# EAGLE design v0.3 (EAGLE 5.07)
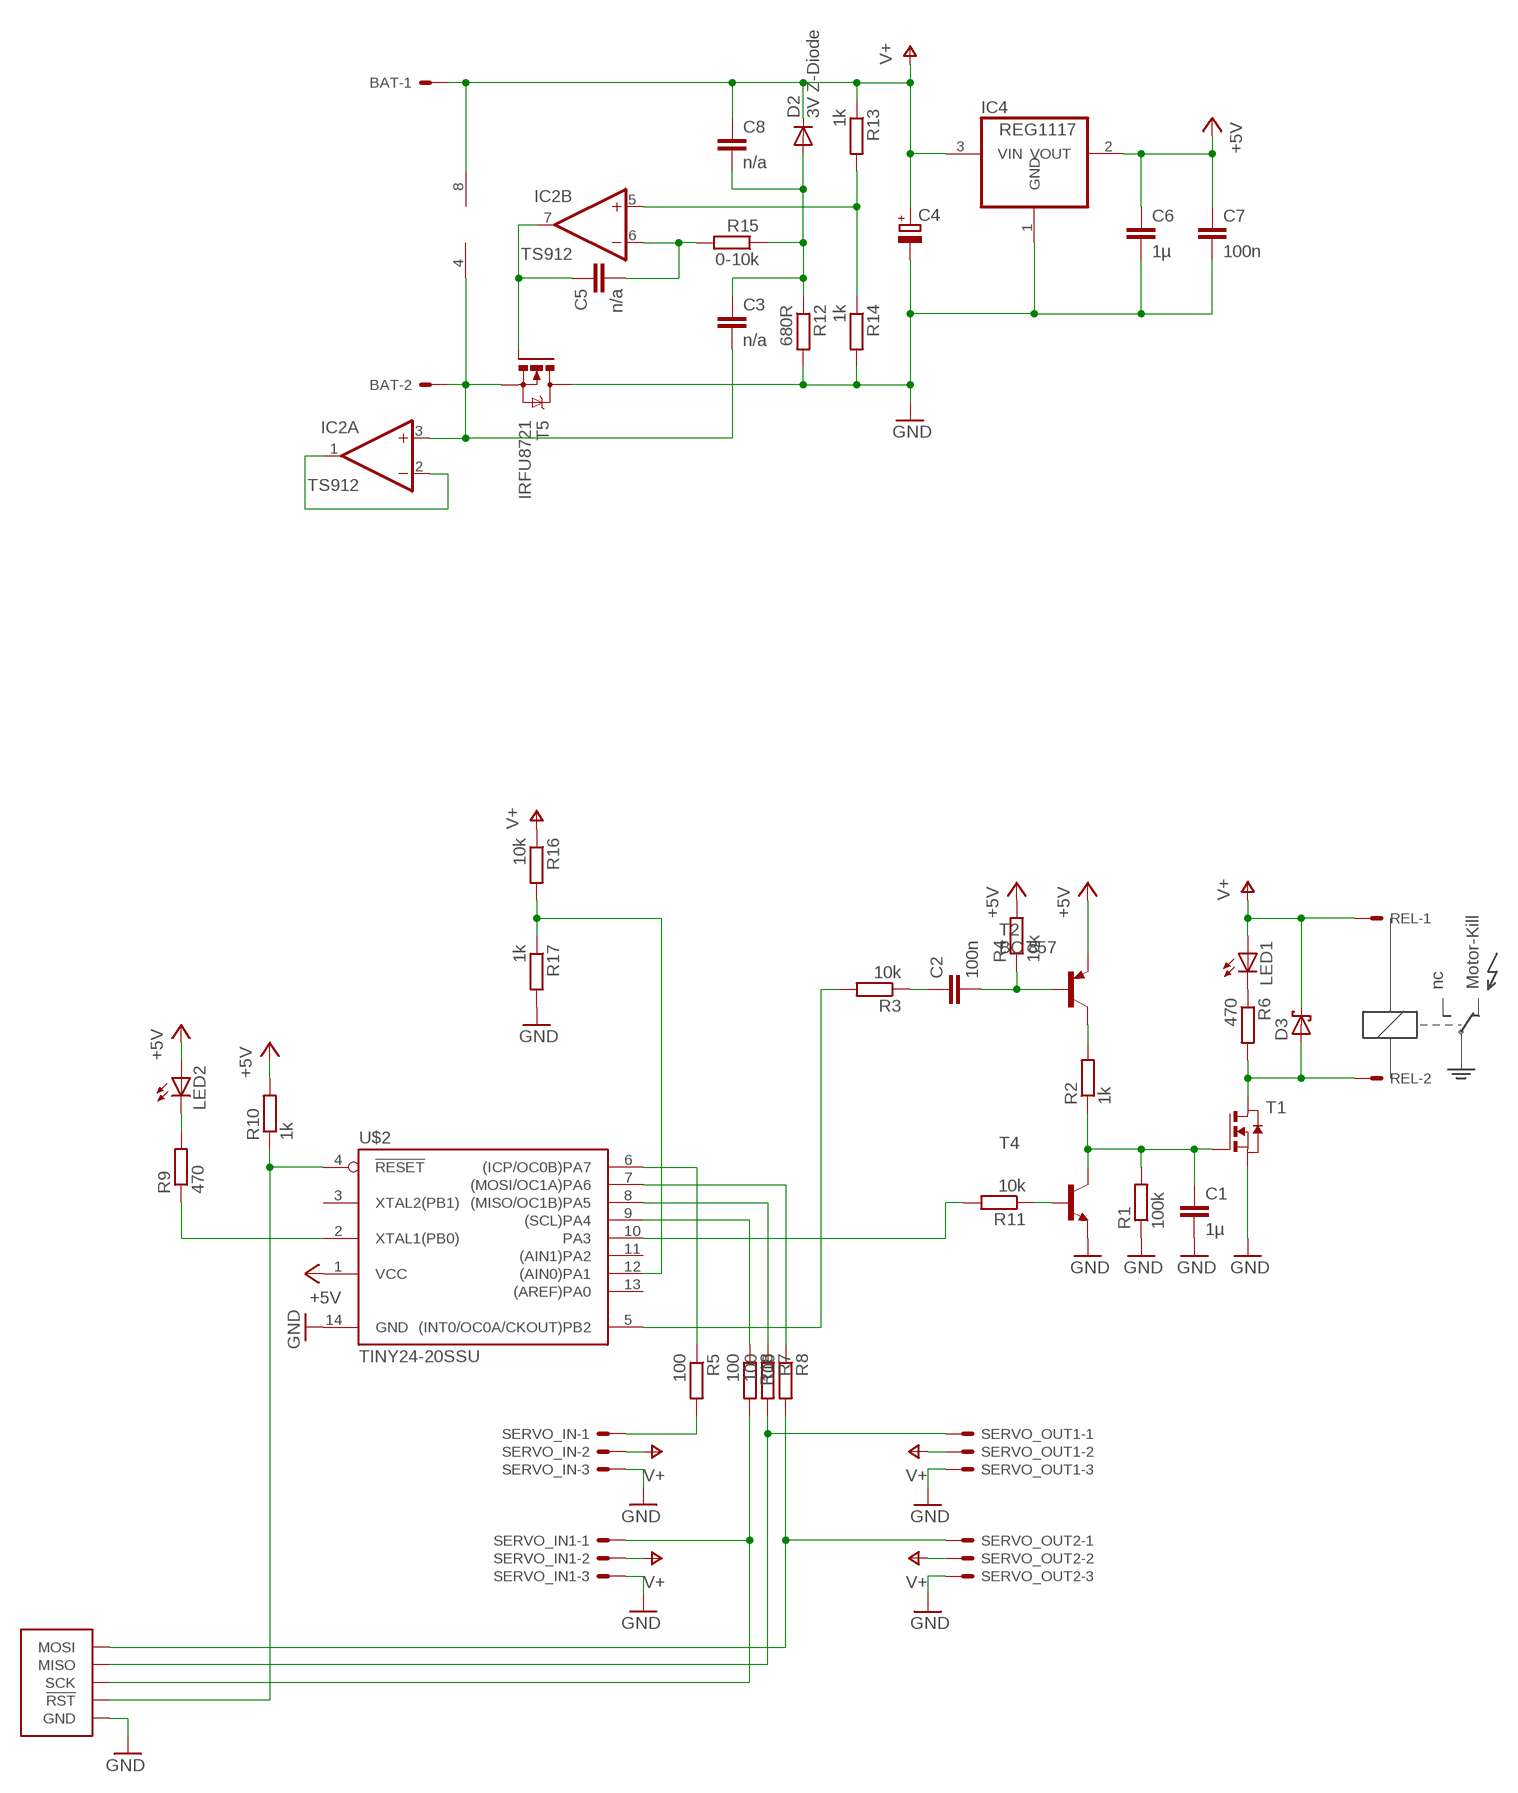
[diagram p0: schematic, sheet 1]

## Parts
BAT  22-23-2021  [22-23-2021]
C1  1µ  C-EUC0805  [C0805]
C2  100n  C-EUC0805  [C0805]
C3  n/a  C-EUC0805K  [C0805K]
C4  CPOL-EUE2.5-7  [E2,5-7]
C5  n/a  C-EUC0805K  [C0805K]
C6  1µ  C-EUC0805  [C0805]
C7  100n  C-EUC0805  [C0805]
C8  n/a  C-EUC0805K  [C0805K]
D2  3V Z-Diode  DIODE-MINIMELF  [MINIMELF]
D3  SCHOTTKY-DIODESMD  [SMB]
IC2  TS912  TL062D  [SO08]
IC4  REG1117  [SOT223]
LED1  LED5MM  [LED5MM]
LED2  LED5MM  [LED5MM]
R1  100k  R-EU_M0805  [M0805]
R2  1k  R-EU_M0805  [M0805]
R3  10k  R-EU_M0805  [M0805]
R4  10k  R-EU_M0805  [M0805]
R5  100  R-EU_M0805  [M0805]
R6  470  R-EU_M0805  [M0805]
R7  100  R-EU_M0805  [M0805]
R8  100  R-EU_M0805  [M0805]
R9  470  R-EU_M0805  [M0805]
R10  1k  R-EU_M0805  [M0805]
R11  10k  R-EU_M0805  [M0805]
R12  680R  R-EU_M0805  [M0805]
R13  1k  R-EU_M0805  [M0805]
R14  1k  R-EU_M0805  [M0805]
R15  0-10k  R-EU_M0805  [M0805]
R16  10k  R-EU_M0805  [M0805]
R17  1k  R-EU_M0805  [M0805]
R18  100  R-EU_M0805  [M0805]
REL  22-23-2021  [22-23-2021]
SERVO_IN  22-23-2031  [22-23-2031]
SERVO_IN1  22-23-2031  [22-23-2031]
SERVO_OUT1  22-23-2031  [22-23-2031]
SERVO_OUT2  22-23-2031  [22-23-2031]
T1  NMOSSOT23  [SOT-23]
T2  BC 857  BC857BSMD  [SOT23-BEC]
T4  BC817-40SMD  [SOT23-BEC]
T5  IRFU8721  [TO251AAV]
U$1  AVR-PROG  [2MM-HEADER]
U$2  TINY24-20SSU  [14S1]

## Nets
+5V: C6.1 C7.1 IC4.2(VOUT) LED2.A R4.2 R10.2 T2.E U$2.1(VCC)
AD_V+: R16.2 R17.1 U$2.12((AIN0)PA1)
GND: C1.2 C4.- C6.2 C7.2 IC4.1(GND) R1.1 R12.2 R14.2 R17.2 SERVO_IN1.3 SERVO_IN.3 SERVO_OUT1.3 SERVO_OUT2.3 T1.2(S) T4.E T5.2(D0) U$1.GND U$2.14(GND)
IN-: BAT.2 C3.2 IC2.3(A:+IN) IC2.4(P:V-) T5.3(S0)
N$1: C1.1 R1.2 R2.1 T1.3(G) T4.C
N$2: D3.A R6.2 REL.2 T1.1(D)
N$3: R2.2 T2.C
N$4: C2.2 R4.1 T2.B
N$5: C2.1 R3.1
N$6: R3.2 U$2.5((INT0/OC0A/CKOUT)PB2)
N$7: R5.1 U$2.6((ICP/OC0B)PA7)
N$8: R5.2 SERVO_IN.1
N$9: R8.2 SERVO_OUT2.1 U$1.MOSI
N$10: R7.2 SERVO_OUT1.1 U$1.MISO
N$11: LED1.K(C) R6.1
N$12: R9.1 U$2.2(XTAL1(PB0))
N$13: R8.1 U$2.7((MOSI/OC1A)PA6)
N$14: LED2.K(C) R9.2
N$15: R7.1 U$2.8((MISO/OC1B)PA5)
N$16: R10.1 U$1./RST(!RST) U$2.4(!RESET)
N$17: R11.1 T4.B
N$18: R11.2 U$2.10(PA3)
N$19: IC2.5(B:+IN) R13.2 R14.1
N$20: R18.1 U$2.9((SCL)PA4)
N$21: C3.1 C8.2 D2.A R12.1 R15.1
N$22: C5.2 IC2.6(B:-IN) R15.2
N$23: C5.1 IC2.7(B:OUT) T5.1(G)
N$24: IC2.1(A:OUT) IC2.2(A:-IN)
N$27: R18.2 SERVO_IN1.1 U$1.SCK
V+: BAT.1 C4.+ C8.1 D2.C D3.C IC2.8(P:V+) IC4.3(VIN) LED1.A R13.1 R16.1 REL.1 SERVO_IN1.2 SERVO_IN.2 SERVO_OUT1.2 SERVO_OUT2.2
Unconnected: U$2.3(XTAL2(PB1)) U$2.11((AIN1)PA2) U$2.13((AREF)PA0)

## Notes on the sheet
- nc | Motor-Kill

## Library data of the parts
BAT REL = con-molex:22-23-2021: .100" (2.54mm) Center Header - 2 Pin
C1-C3 C5-C8 = rcl:C-EU: CAPACITOR, European symbol
C4 = rcl:CPOL-EU: POLARIZED CAPACITOR, European symbol
D2 = diode:DIODE-: DIODE
D3 = diode:SCHOTTKY-DIODE: Schottky Diode
IC2 = linear:TL062: OP AMP
IC4 = burr-brown:REG1117: 800mA and 1A Low Dropout (LDO) Positive Regulator 1.8V, 2.5V, 2.85V, 3.3V, 5V, and Adj
LED1 LED2 = led:LED: LED
R1-R18 = rcl:R-EU_: RESISTOR, European symbol
SERVO_IN SERVO_IN1 SERVO_OUT1 SERVO_OUT2 = con-molex:22-23-2031: .100" (2.54mm) Center Header - 3 Pin
T1 = zetex:NMOSSOT23: MOS FET
T2 = transistor-pnp:BC857*: PNP Transistror
T4 = transistor-npn:BC817*: NPN Transistor
T5 = FET:IRFU8721
U$1 = AVR-prog:AVR-PROG
U$2 = atmel:TINY24

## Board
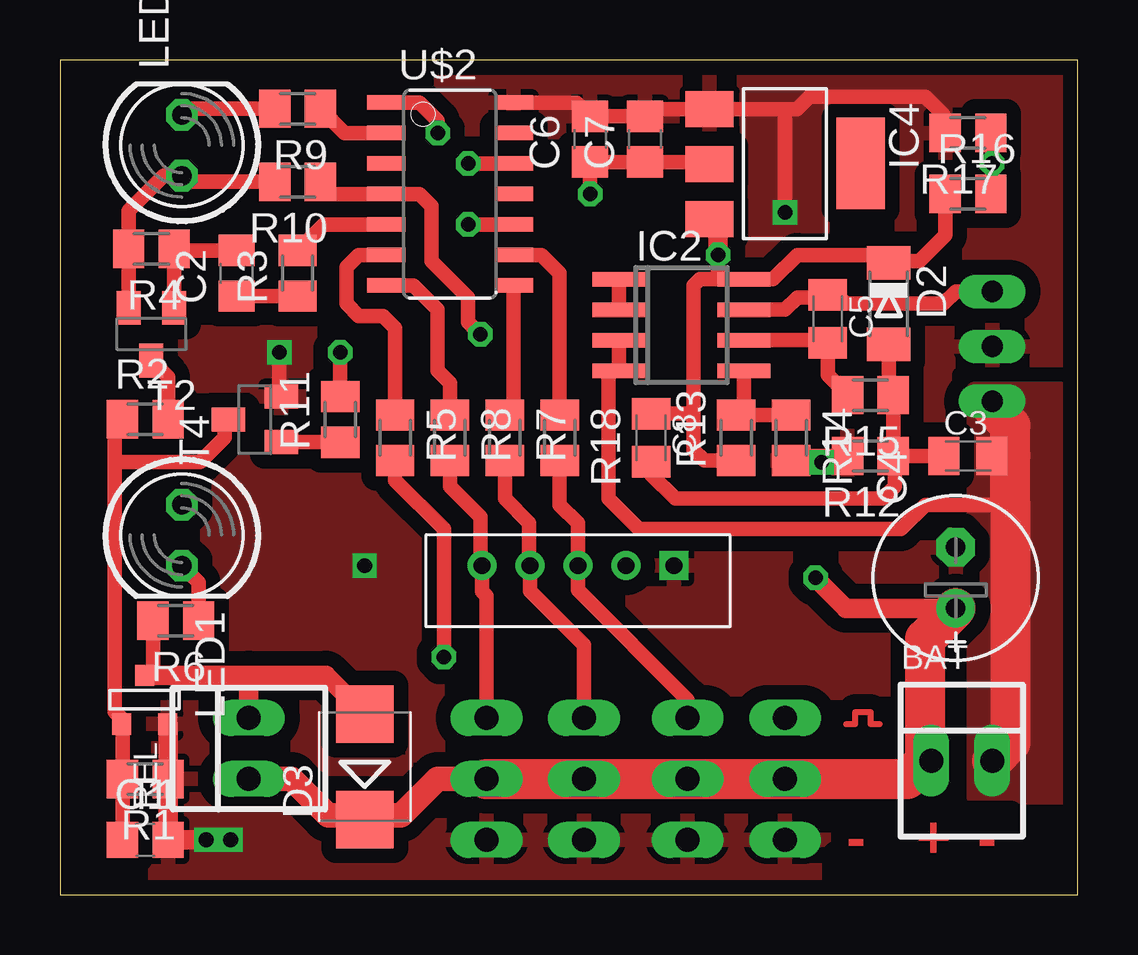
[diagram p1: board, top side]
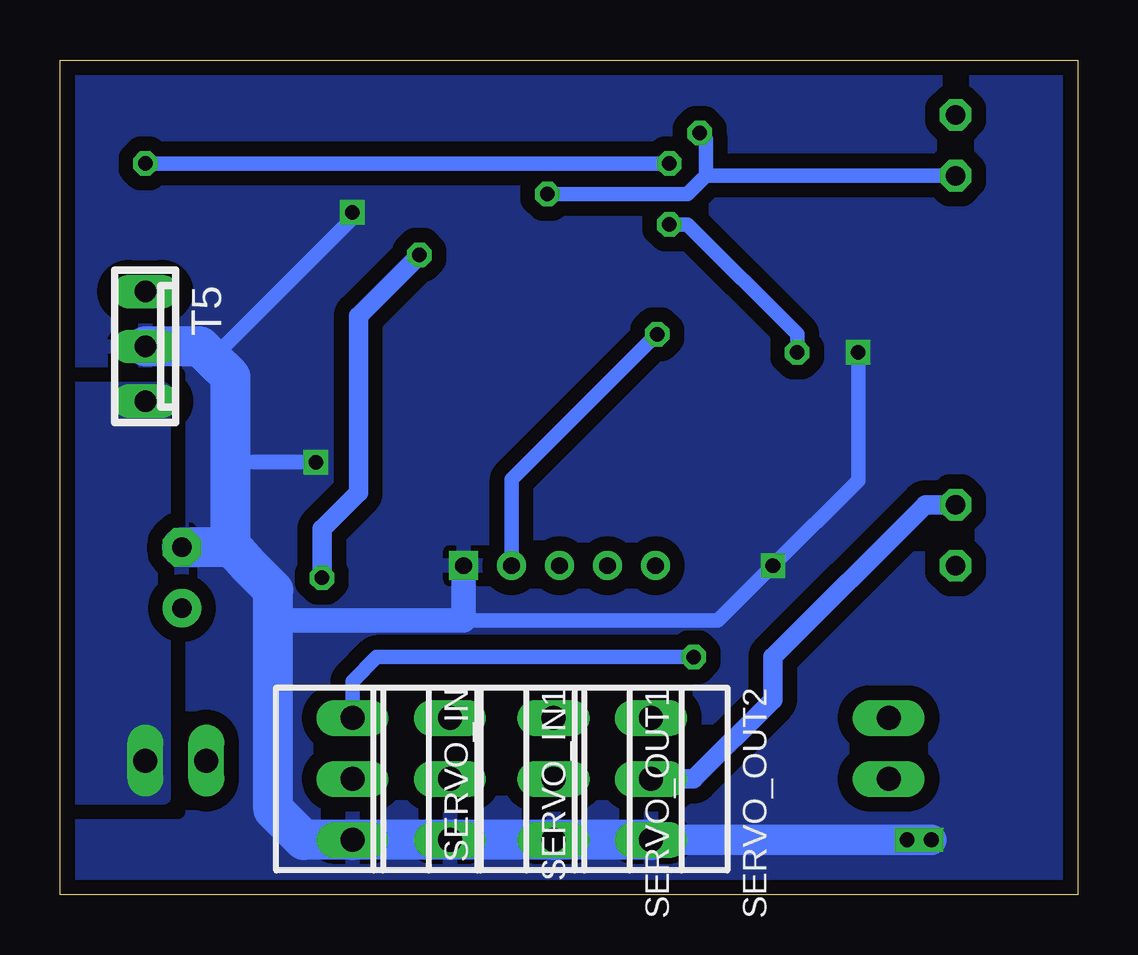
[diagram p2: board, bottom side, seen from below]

Size 42.42 x 34.8 mm. Coordinates in mm from the lower left corner, seen from the top.
Outline: 0,0 42.42,0 42.42,34.8 0,34.8 0,0
Copper layers (1*16): Top 0.035mm / dielectric 1.5mm / Bottom 0.035mm
Design rules "default *": minimum track width 10mil, minimum drill 24mil, track to track 10mil, track to pad 10mil, pad to pad 10mil, via to via 10mil, smd to smd 0mil, copper to edge 5mil, drill to drill 10mil, minimum pad ring 10mil, minimum via ring 8mil, stop-mask expansion 4mil, vias tented up to drill 0mil, thermal gap 10mil
tRestrict: area 32.4,0.6 to 41,1.7

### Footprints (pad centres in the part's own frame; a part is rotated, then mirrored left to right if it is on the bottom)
22-23-2021 = drill 1 long: 1 -1.27,0; 2 1.27,0
C0805 = smd 1.3 x 1.5: 1 -0.95,0; 2 0.95,0
C0805K = smd 1.3 x 1.6: 1 -1,0; 2 1,0
E2,5-7 = drill 0.813 pad 1.6 round: + -1.27,0 | drill 0.813 pad 1.6 octagon: - 1.27,0
MINIMELF = smd 1.4 x 1.8: A 1.7,0; C -1.7,0
SMB = smd 2.4 x 2.4: A 2.2,0; C -2.2,0
SO08 = smd 0.6 x 2.2: 1 -1.905,-2.6; 2 -0.635,-2.6; 3 0.635,-2.6; 4 1.905,-2.6; 5 1.905,2.6; 6 0.635,2.6; 7 -0.635,2.6; 8 -1.905,2.6
SOT223 = smd 1.499 x 2.007: 1 -2.261,-3.15; 2 0.025,-3.15; 3 2.311,-3.15 | smd 3.81 x 2.007: 4 0,3.15
LED5MM = drill 0.813 octagon: A -1.27,0; K 1.27,0
M0805 = smd 1.3 x 1.6: 1 -0.95,0; 2 0.95,0
22-23-2031 = drill 1 long: 1 -2.54,0; 2 0,0; 3 2.54,0
SOT-23 = smd 0.787 x 0.889: 1 0.025,-1.016; 2 -0.94,1.016; 3 0.991,1.016
SOT23-BEC = smd 1 x 1.4: B -0.95,-1.1; C 0,1.1; E 0.95,-1.1
TO251AAV = drill 0.889 long: 1 -2.286,0; 2 0,0; 3 2.286,0
2MM-HEADER = drill 0.7 round: /RST 0,-2; MISO 0,2; MOSI 0,4; SCK 0,0 | drill 0.7 square: GND 0,-4
14S1 = smd 0.6 x 1.6: 1 -3.81,-2.654; 2 -2.54,-2.654; 3 -1.27,-2.654; 4 0,-2.654; 5 1.27,-2.654; 6 2.54,-2.654; 7 3.81,-2.654; 8 3.81,2.654; 9 2.54,2.654; 10 1.27,2.654; 11 0,2.654; 12 -1.27,2.654; 13 -2.54,2.654; 14 -3.81,2.654

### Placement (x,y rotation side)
BAT  37.59,5.59 0 top
C1  3.56,2.29 0 top
C2  7.37,25.91 90 top
C3  37.85,18.29 0 top
C4  37.34,13.21 90 top
C5  32,24 270 top
C6  22.1,31.5 90 top
C7  24.38,31.5 90 top
C8  24.64,19.05 270 top
D2  34.54,24.64 270 top
D3  12.7,5.33 90 top
IC2  25.91,23.75 270 top
IC4  30.23,30.48 270 top
LED1  5.08,14.99 270 top
LED2  5.08,31.24 90 top
R1  3.56,4.83 180 top
R2  3.56,19.81 0 top
R3  9.91,25.91 90 top
R4  3.81,26.92 180 top
R5  13.97,19.05 270 top
R6  4.83,11.43 180 top
R7  18.54,19.05 270 top
R8  16.26,19.05 270 top
R9  9.91,32.77 180 top
R10  9.91,29.72 180 top
R11  11.68,19.81 90 top
R12  33.78,18.29 180 top
R13  28.19,19.05 90 top
R14  30.48,19.05 270 top
R15  33.78,20.83 180 top
R16  37.85,29.21 0 top
R17  37.85,31.75 180 top
R18  20.83,19.05 270 top
REL  7.87,6.1 90 top
SERVO_IN  30.23,4.83 270 bottom
SERVO_IN1  26.16,4.83 270 bottom
SERVO_OUT1  21.84,4.83 270 bottom
SERVO_OUT2  17.78,4.83 270 bottom
T1  3.56,8.13 180 top
T2  3.81,23.37 180 top
T4  8.13,19.81 90 top
T5  38.86,22.86 270 bottom
U$1  21.59,13.72 90 top
U$2  16.26,29.21 270 top

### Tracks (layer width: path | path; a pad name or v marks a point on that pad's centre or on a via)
+5V  (via drill 0.61)
  Top 0.61: R10.2 5.33,29.72 LED2.A 4.32,29.97 2.86,28.51 R4.2 T2.E | IC4.2 26.98,30.55 C7.1 C6.1 v22.1,29.21 | v15.75,31.75 15.75,32.26 14.99,33.02 U$2.1
  Bottom 0.61: v22.1,29.21 16.26,29.21 15.49,29.97 | LED2.A 15.49,29.97 | 15.49,29.97 15.49,31.5 v15.75,31.75
AD_V+  (via drill 0.61)
  Top 0.61: v17.02,30.48 U$2.12 | R16.2 38.86,29.28 v38.86,30.48 38.86,31.68 R17.1
  Bottom 0.61: v17.02,30.48 v38.86,30.48
GND  (via drill 0.61)
  Top 0.61: 30.23,32.74 IC4.1 24.68,32.74 C7.2 C6.2 21.52,33.02 U$2.14 | R17.2 36.83,31.82 36.83,32.51 36.07,33.27 31.24,33.27 30.71,32.74 30.23,32.74 | v30.23,28.45 30.23,32.74 | T4.E 9.14,20.85 v9.14,22.61 | R14.2 30.41,18.29 R12.2 31.75,18.29 v31.75,18.03
  Top 0.813: T1.2 R1.1 C1.2 v6.1,2.29 v7.11,2.29
  Bottom 0.61: v30.23,28.45 30.23,28.19 36.07,22.35 | v9.14,22.61 9.14,17.27 v12.7,13.72 14.99,11.43 25.59,11.43 | 35.31,18.03 v31.75,18.03
  Bottom 1.016: 33.53,11.43 25.59,11.43 U$1.GND
  Bottom 1.27: v6.1,2.29 v7.11,2.29 SERVO_OUT2.3
  Bottom 1.676: 35.22,14.48 34.55,13.72 33.53,12.7 33.53,11.43 33.53,3.56 32.26,2.29 SERVO_IN.3 SERVO_IN1.3 SERVO_OUT1.3 SERVO_OUT2.3 | 35.22,14.48 C4.- | 35.22,14.48 35.31,14.48 35.31,18.03 35.31,21.59 36.07,22.35 36.58,22.86 T5.2
  pour Bottom (isolate 0.61, rank 2): 0,34.8 42.42,34.8 42.42,0 0,0
  pour Top (isolate 0.61, rank 2): 0,34.8 42.42,34.8 42.42,0 0,0
IN-
  Top 0.61: 39.62,16.26 36.07,16.26 35.05,15.24 24.13,15.24 22.86,16.51 22.86,21.84 IC2.4 IC2.3 | 39.62,18.29 C3.2
  Top 1.27: 38.86,20.32 T5.3
  Top 1.676: 38.86,20.32 39.62,19.56 39.62,18.29 39.62,16.26 39.62,6.35 BAT.2
  pour Bottom (isolate 0.61, no thermals): 38.1,21.08 42.42,21.08 42.42,4.06 38.1,4.06
  pour Top (isolate 0.61, no thermals): 38.1,21.08 42.42,21.08 42.42,4.06 38.1,4.06
N$1
  Top 0.61: C1.1 R1.2 2.61,7.07 T1.3 2.56,7.34 2.29,7.62 2.29,18.03 | R2.1 2.29,19.49 2.29,18.03 | T4.C 6.86,19.64 6.86,19.05 5.84,18.03 2.29,18.03
N$2
  Top 0.61: R6.2 3.88,9.33 4.06,9.14
  Top 0.813: T1.1 4.06,9.14 7.87,9.14 | 7.87,9.14 11.09,9.14 D3.A | 7.87,9.14 REL.2
N$3
  Top 0.61: T2.C 4.51,21.57 R2.2
N$4
  Top 0.61: C2.2 4.83,26.86 R4.1 T2.B
N$5
  Top 0.61: C2.1 R3.1
N$6
  Top 0.61: U$2.5 10.99,27.94 R3.2
N$7
  Top 0.61: R5.1 13.97,23.62 13.46,24.13 12.45,24.13 11.94,24.64 11.94,26.16 12.45,26.67 U$2.6
N$8  (via drill 0.61)
  Top 0.61: R5.2 13.97,17.27 16,15.24 v16,9.91
  Bottom 0.61: v16,9.91 29.21,9.91 30.23,8.89 SERVO_IN.1
N$9
  Top 0.61: R8.2 16.26,17.02 17.53,15.75 17.53,13.78 U$1.MOSI 17.59,12.64 17.78,12.45 SERVO_OUT2.1
N$10
  Top 0.61: R7.2 18.54,16.51 19.56,15.49 19.56,13.75 U$1.MISO 19.59,12.67 21.84,10.41 SERVO_OUT1.1
N$11
  Top 0.61: R6.1 5.78,13.02 LED1.K
N$12
  Top 0.61: R9.1 11.87,31.75 U$2.2
N$13
  Top 0.61: U$2.7 14.73,25.4 15.75,24.38 15.75,21.84 16.26,21.34 R8.1
N$14
  Top 0.61: R9.2 5.33,32.77 LED2.K
N$15
  Top 0.61: R7.1 18.91,20.39 U$2.8
N$16  (via drill 0.61)
  Top 0.61: R10.1 11.36,29.21 U$2.4 14.99,29.21 15.49,28.7 15.49,26.42 17.02,24.89 17.02,23.88 v17.53,23.37
  Bottom 0.61: v17.53,23.37 23.59,17.3 U$1./RST
N$17
  Top 0.61: T4.B R11.1
N$18  (via drill 0.61)
  Top 0.61: R11.2 v11.68,22.61 | v17.02,27.94 U$2.10
  Bottom 0.61: v11.68,22.61 11.68,23.37 16.26,27.94 v17.02,27.94
N$19
  Top 0.61: R13.2 28.45,20 | 28.45,20 R14.1 | IC2.5 28.51,20.06 28.45,20
N$20
  Top 0.61: U$2.9 20.07,26.67 20.83,25.91 R18.1
N$21
  Top 0.61: D2.A 34.54,20.64 R15.1 R12.1 | R12.1 C3.1 | C8.2 24.64,17.53 25.65,16.51 34.29,16.51 34.8,17.02 34.8,18.22 R12.1
N$22
  Top 0.61: IC2.6 31.86,23.11 C5.2 32,21.66 R15.2
N$23
  Top 0.61: IC2.7 30.23,24.38 30.73,24.89 31.89,24.89 C5.1 32.4,25 32.77,24.64 36.83,24.64 37.34,25.15 T5.1
N$24
  Top 0.61: IC2.2 IC2.1
N$25
  Top 0.254: 32.77,7.11 33.15,7.11 33.15,7.62 33.78,7.62 33.78,7.11 34.16,7.11
N$27
  Top 0.61: R18.2 20.83,16.26 21.59,15.49 U$1.SCK 21.59,12.7 26.16,8.13 SERVO_IN1.1
V+  (via drill 0.61)
  Top 0.61: R16.1 36.9,27.5 35.81,26.42 34.62,26.42 D2.C 34.21,26.67 30.73,26.67 29.72,25.65 IC2.8 27.43,25.65 | 27.43,25.65 26.67,25.65 26.42,25.4 26.42,20.07 | v27.43,26.67 27.43,25.65 | R13.1 26.86,18.1 26.42,18.54 26.42,20.07 | C8.1 26.4,20.05 26.42,20.07
  Top 0.813: C4.+ 32.77,11.94 v31.5,13.21 | IC4.3 27.43,28.17 v27.43,26.67
  Top 1.016: REL.1 9.65,4.83 11.18,3.3 12.28,3.3 D3.C 12.61,3.3 14.22,3.3 15.75,4.83 SERVO_OUT2.2
  Top 1.422: 36.07,5.59 BAT.1
  Top 1.676: C4.+ 36.07,10.67 36.07,5.59 35.31,4.83 SERVO_IN.2 SERVO_IN1.2 | SERVO_IN1.2 SERVO_OUT2.2 SERVO_OUT1.2 SERVO_IN1.2
  Bottom 0.813: LED1.A 6.35,16.26 12.7,9.91 12.7,8.13 16,4.83 SERVO_OUT2.2 | v27.43,26.67 29.97,24.13 29.97,16.76 31.5,15.24 v31.5,13.21

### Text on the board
Top: - | + | -
tStop: OOIS | + | - | + | -
tCream: OOIS | + | - | + | -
